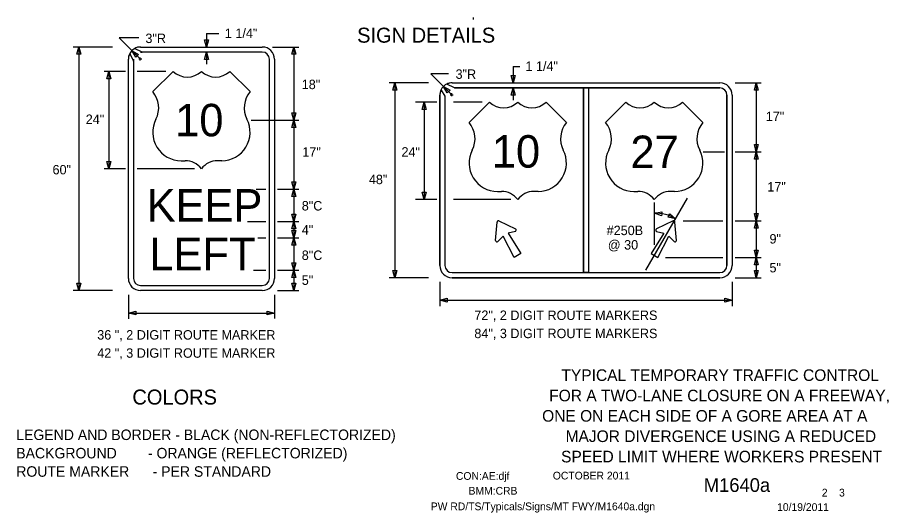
# Model space of a CAD drawing. Extents: x 16512 to 19504, y 5761 to 6984.
# Drawn here: x 17768 to 18466, y 5932 to 6328 of the extents above; entities that cross this region are included whole.
import ezdxf

# ---------------------------------------------------------------- set-up
doc = ezdxf.new("R2010")
doc.units = 0
for name, color, linetype in [('ALI_LEGAL_EX', 7, 'Continuous'), ('BORDER', 7, 'Continuous'), ('BORDER_SIGNAL_WO', 7, 'Continuous'), ('TRAFFIC_SIGNS_PR', 7, 'Continuous'), ('TYPICAL_EX', 7, 'Continuous'), ('TYPICAL_TEXT_DIMEN_PR', 7, 'Continuous')]:
    doc.layers.add(name, color=color, linetype=linetype)

msp = doc.modelspace()

# ---------------------------------------------------------------- linework, layer by layer
at = {"layer": 'ALI_LEGAL_EX'}
msp.add_lwpolyline([(18133.42, 6328.26), (18133.42, 6326.51)], dxfattribs=at)
at = {"layer": 'TRAFFIC_SIGNS_PR'}
for p, q in [((17859.5, 6300.96), (17858.5, 6299.45)), ((17868.29, 6300.52), (17862.19, 6303.27)), ((17867.09, 6304.58), (17964.59, 6304.58)), ((17857.34, 6119.33), (17857.34, 6294.83)), ((17858.53, 6299.39), (17861.4, 6293.35)), ((17861.4, 6294.83), (17861.4, 6119.33)), ((17964.59, 6300.52), (17867.09, 6300.52)), ((17970.27, 6119.33), (17970.27, 6294.83)), ((17974.34, 6294.83), (17974.34, 6119.33)), ((18118.56, 6271.83), (18112.33, 6274.85)), ((18116.61, 6275.88), (18331.11, 6275.88)), ((18116.61, 6275.88), (18331.11, 6275.88)), ((18106.86, 6266.13), (18106.86, 6129.63)), ((18106.86, 6129.63), (18106.86, 6266.13)), ((18107.78, 6270.14), (18110.91, 6265.1)), ((18118.55, 6271.82), (18221.83, 6271.82)), ((18331.11, 6271.82), (18118.55, 6271.82)), ((18221.83, 6271.82), (18221.83, 6123.95)), ((18225.89, 6271.82), (18225.89, 6123.95)), ((18225.89, 6271.82), (18331.11, 6271.82)), ((18336.8, 6266.13), (18336.8, 6220.38)), ((18336.8, 6129.63), (18336.8, 6266.13)), ((18340.86, 6266.13), (18340.86, 6129.63)), ((18340.86, 6266.13), (18340.86, 6129.63)), ((18110.92, 6265.08), (18110.92, 6129.63)), ((18110.92, 6265.08), (18110.92, 6129.63)), ((18336.8, 6220.38), (18336.8, 6129.63)), ((18151.46, 6149.74), (18152.61, 6164.46)), ((18154.12, 6165.33), (18167.44, 6158.97)), ((18293.59, 6165.33), (18280.28, 6158.97)), ((18296.26, 6149.74), (18295.1, 6164.46)), ((18116.61, 6123.95), (18331.11, 6123.95)), ((18116.61, 6119.88), (18331.11, 6119.88)), ((18331.11, 6119.88), (18116.61, 6119.88)), ((17867.09, 6113.64), (17964.59, 6113.64)), ((17964.59, 6109.58), (17867.09, 6109.58))]:
    msp.add_line(p, q, dxfattribs=at)
for points in [[(18118.55, 6271.82), (18118.53, 6271.83)], [(18110.91, 6265.1), (18110.92, 6265.08)], [(18167.28, 6157), (18161.55, 6155.42), (18171.77, 6139.25), (18166.37, 6136.13), (18157.48, 6153.07), (18153.25, 6148.9)], [(18280.44, 6157), (18286.16, 6155.42), (18275.95, 6139.25), (18281.34, 6136.13), (18290.24, 6153.07), (18294.46, 6148.9)]]:
    msp.add_lwpolyline(points, dxfattribs=at)
msp.add_lwpolyline([(18221.83, 6271.82), (18225.89, 6271.82), (18225.89, 6123.95), (18221.83, 6123.95)], close=True, dxfattribs=at)
for centre, radius, start, end in [((17867.09, 6294.83), 9.75, 90, 180), ((17866.5, 6297.01), 7.6, 85.58319, 124.53531), ((17964.59, 6294.83), 9.75, 0, 90), ((17864.37, 6295.43), 7.06, 145.86811, 184.82317), ((17855.94, 6294.09), 5.51, 352.24294, 7.75653), ((17867.69, 6304.95), 4.47, 262.2432, 277.7568), ((17964.59, 6294.83), 5.69, 0, 90), ((18116.61, 6266.13), 9.75, 90, 180), ((18116.61, 6266.13), 9.75, 90, 180), ((18115.93, 6269.32), 6.6, 84.11162, 123.06374), ((18331.11, 6266.13), 9.75, 0, 90), ((18331.11, 6266.13), 9.75, 0, 90), ((18112.99, 6266.84), 6.17, 147.60925, 186.56283), ((18117.55, 6279), 7.24, 277.81035, 278.05403), ((18331.11, 6266.13), 5.69, 0, 89.99421), ((18331.11, 6266.13), 5.69, 0, 90), ((18153.67, 6164.37), 1.06, 64.48226, 175.51774), ((18294.05, 6164.37), 1.06, 4.48226, 115.51774), ((18166.98, 6158.02), 1.06, 285.9885, 64.48226), ((18280.73, 6158.02), 1.06, 115.51774, 254.0115), ((18152.52, 6149.66), 1.06, 175.51775, 314.01151), ((18295.2, 6149.66), 1.06, 225.98849, 4.48225), ((18116.61, 6129.63), 9.75, 180, 270), ((18116.61, 6129.63), 9.75, 180, 270), ((18116.61, 6129.63), 5.69, 180, 270), ((18116.61, 6129.63), 5.69, 180, 270), ((18331.11, 6129.63), 9.75, 270, 0), ((18331.11, 6129.63), 5.69, 270, 0), ((18331.11, 6129.63), 9.75, 270, 0), ((18331.11, 6129.63), 5.69, 270, 0), ((17867.09, 6119.33), 9.75, 180, 270), ((17867.09, 6119.33), 5.69, 180, 270), ((17964.59, 6119.33), 5.69, 270, 0), ((17964.59, 6119.33), 9.75, 270, 0)]:
    msp.add_arc(centre, radius, start, end, dxfattribs=at)
at = {"layer": 'TYPICAL_EX'}
for p, q in [((17876.84, 6268.84), (17893.09, 6285.09)), ((17954.84, 6268.84), (17938.59, 6285.09)), ((18130.22, 6244.22), (18146.47, 6260.47)), ((18208.22, 6244.22), (18191.97, 6260.47)), ((18239.5, 6244.22), (18255.75, 6260.47)), ((18317.5, 6244.22), (18301.25, 6260.47)), ((17899.56, 6213.54), (17902.81, 6213.54)), ((17932.11, 6213.54), (17928.86, 6213.54)), ((18152.95, 6188.93), (18156.2, 6188.93)), ((18185.49, 6188.93), (18182.24, 6188.93)), ((18262.22, 6188.93), (18265.47, 6188.93)), ((18294.77, 6188.93), (18291.52, 6188.93))]:
    msp.add_line(p, q, dxfattribs=at)
for centre, radius, start, end in [((17904.46, 6296.92), 16.42, 226.14041, 313.85958), ((17927.21, 6296.92), 16.42, 226.14042, 313.85959), ((17861.44, 6255.82), 20.16, 333.09768, 40.19361), ((17970.24, 6255.82), 20.16, 139.80639, 206.90233), ((18157.85, 6272.31), 16.42, 226.14041, 313.85958), ((18180.59, 6272.31), 16.42, 226.14042, 313.85959), ((18267.12, 6272.31), 16.42, 226.14041, 313.85958), ((18289.87, 6272.31), 16.42, 226.14042, 313.85959), ((17899.6, 6236.27), 22.73, 152.6698, 269.90132), ((17932.07, 6236.27), 22.73, 270.09868, 27.3302), ((18114.82, 6231.21), 20.16, 333.09768, 40.19361), ((18223.62, 6231.21), 20.16, 139.80639, 206.90233), ((18224.1, 6231.21), 20.16, 333.09768, 40.19361), ((18332.9, 6231.21), 20.16, 139.80639, 206.90233), ((18152.99, 6211.66), 22.73, 152.6698, 269.90132), ((18185.45, 6211.66), 22.73, 270.09868, 27.3302), ((18262.27, 6211.66), 22.73, 152.6698, 269.90132), ((18294.73, 6211.66), 22.73, 270.09868, 27.3302), ((17902.85, 6197.26), 16.28, 37.1038, 90.13853), ((17928.82, 6197.26), 16.28, 89.86147, 142.8962), ((18156.24, 6172.65), 16.28, 37.1038, 90.13853), ((18182.2, 6172.65), 16.28, 89.86147, 142.8962), ((18265.52, 6172.65), 16.28, 37.1038, 90.13853), ((18291.48, 6172.65), 16.28, 89.86147, 142.8962)]:
    msp.add_arc(centre, radius, start, end, dxfattribs=at)
at = {"layer": 'TYPICAL_TEXT_DIMEN_PR'}
for p, q in [((17919.81, 6315.34), (17919.81, 6304.58)), ((17919.81, 6315.34), (17929.91, 6315.34)), ((17865.71, 6311.86), (17850.05, 6311.86)), ((17850.05, 6311.86), (17860.29, 6301.63)), ((17919.81, 6304.58), (17918.24, 6310.44)), ((17918.24, 6310.44), (17919.81, 6310.44)), ((17919.81, 6310.44), (17921.38, 6310.44)), ((17921.38, 6310.44), (17919.81, 6304.58)), ((17844.51, 6304.58), (17813.21, 6304.58)), ((17815.98, 6298.72), (17817.55, 6304.58)), ((17817.55, 6304.58), (17817.55, 6109.58)), ((17817.55, 6304.58), (17819.12, 6298.72)), ((17860.29, 6301.63), (17866.85, 6295.07)), ((17863.32, 6296.37), (17860.29, 6301.63)), ((17860.29, 6301.63), (17865.54, 6298.6)), ((17972.88, 6304.58), (17993.84, 6304.58)), ((17988.37, 6298.72), (17989.94, 6304.58)), ((17989.94, 6304.58), (17989.94, 6246.08)), ((17989.94, 6304.58), (17991.51, 6298.72)), ((17817.55, 6298.72), (17815.98, 6298.72)), ((17819.12, 6298.72), (17817.55, 6298.72)), ((17864.43, 6297.49), (17863.32, 6296.37)), ((17865.54, 6298.6), (17864.43, 6297.49)), ((17865.64, 6295.07), (17868.05, 6295.07)), ((17866.85, 6293.86), (17866.85, 6296.28)), ((17918.28, 6294.66), (17919.86, 6300.52)), ((17919.86, 6294.66), (17918.28, 6294.66)), ((17919.86, 6300.52), (17919.86, 6290.77)), ((17919.86, 6300.52), (17921.43, 6294.66)), ((17921.43, 6294.66), (17919.86, 6294.66)), ((17989.94, 6298.72), (17988.37, 6298.72)), ((17991.51, 6298.72), (17989.94, 6298.72)), ((18165.47, 6289.03), (18165.47, 6275.88)), ((18165.47, 6289.03), (18170.99, 6289.03)), ((17854.96, 6285.08), (17837.84, 6285.08)), ((17840.16, 6279.22), (17841.73, 6285.08)), ((17841.73, 6285.08), (17841.73, 6207.08)), ((17841.73, 6285.08), (17843.3, 6279.22)), ((17887.2, 6285.08), (17864.33, 6285.08)), ((18113.75, 6283.17), (18099.57, 6283.17)), ((18099.57, 6283.17), (18109.72, 6273.02)), ((18165.47, 6275.88), (18163.89, 6281.74)), ((18163.89, 6281.74), (18165.47, 6281.74)), ((18165.47, 6281.74), (18167.04, 6281.74)), ((18167.04, 6281.74), (18165.47, 6275.88)), ((17841.73, 6279.22), (17840.16, 6279.22)), ((17843.3, 6279.22), (17841.73, 6279.22)), ((18097.62, 6275.88), (18066.33, 6275.88)), ((18069.1, 6270.02), (18070.67, 6275.88)), ((18070.67, 6275.88), (18070.67, 6119.88)), ((18070.67, 6275.88), (18072.24, 6270.02)), ((18109.72, 6273.02), (18116.37, 6266.37)), ((18112.76, 6267.76), (18109.72, 6273.02)), ((18109.72, 6273.02), (18114.98, 6269.99)), ((18343.23, 6275.88), (18364.19, 6275.88)), ((18358.72, 6270.02), (18360.29, 6275.88)), ((18360.29, 6275.88), (18360.29, 6220.63)), ((18360.29, 6275.88), (18361.86, 6270.02)), ((18070.67, 6270.02), (18069.1, 6270.02)), ((18072.24, 6270.02), (18070.67, 6270.02)), ((18113.87, 6268.88), (18112.76, 6267.76)), ((18114.98, 6269.99), (18113.87, 6268.88)), ((18115.16, 6266.37), (18117.58, 6266.37)), ((18116.37, 6265.16), (18116.37, 6267.58)), ((18163.94, 6265.96), (18165.51, 6271.82)), ((18163.94, 6265.96), (18165.51, 6271.82)), ((18165.51, 6271.82), (18165.51, 6262.07)), ((18165.51, 6271.82), (18167.08, 6265.96)), ((18165.51, 6271.82), (18167.08, 6265.96)), ((18360.29, 6270.02), (18358.72, 6270.02)), ((18361.86, 6270.02), (18360.29, 6270.02)), ((18104.49, 6260.47), (18087.36, 6260.47)), ((18092.65, 6254.61), (18094.23, 6260.47)), ((18094.23, 6260.47), (18094.23, 6182.47)), ((18094.23, 6260.47), (18095.8, 6254.61)), ((18140.59, 6260.47), (18117.71, 6260.47)), ((18165.51, 6265.96), (18163.94, 6265.96)), ((18165.51, 6265.96), (18163.94, 6265.96)), ((18167.08, 6265.96), (18165.51, 6265.96)), ((18167.08, 6265.96), (18165.51, 6265.96)), ((18094.23, 6254.61), (18092.65, 6254.61)), ((18095.8, 6254.61), (18094.23, 6254.61)), ((17955.73, 6246.08), (17993.84, 6246.08)), ((17989.94, 6246.08), (17988.37, 6251.94)), ((17988.37, 6251.94), (17989.94, 6251.94)), ((17988.37, 6240.22), (17989.94, 6246.08)), ((17989.94, 6251.94), (17991.51, 6251.94)), ((17991.51, 6251.94), (17989.94, 6246.08)), ((17989.94, 6246.08), (17989.94, 6190.83)), ((17989.94, 6246.08), (17991.51, 6240.22)), ((17989.94, 6240.22), (17988.37, 6240.22)), ((17991.51, 6240.22), (17989.94, 6240.22)), ((18360.29, 6220.63), (18358.72, 6226.49)), ((18358.72, 6226.49), (18360.29, 6226.49)), ((18360.29, 6226.49), (18361.86, 6226.49)), ((18361.86, 6226.49), (18360.29, 6220.63)), ((18317.67, 6220.63), (18334.82, 6220.63)), ((18343.23, 6220.63), (18364.19, 6220.63)), ((18358.72, 6214.77), (18360.29, 6220.63)), ((18360.29, 6220.63), (18360.29, 6165.38)), ((18360.29, 6220.63), (18361.86, 6214.77)), ((17841.73, 6207.08), (17840.16, 6212.94)), ((17840.16, 6212.94), (17841.73, 6212.94)), ((17841.73, 6212.94), (17843.3, 6212.94)), ((17843.3, 6212.94), (17841.73, 6207.08)), ((18360.29, 6214.77), (18358.72, 6214.77)), ((18361.86, 6214.77), (18360.29, 6214.77)), ((17854.96, 6207.08), (17837.84, 6207.08)), ((17910.33, 6207.08), (17864.33, 6207.08)), ((17989.94, 6190.83), (17988.37, 6196.69)), ((17988.37, 6196.69), (17989.94, 6196.69)), ((17989.94, 6196.69), (17991.51, 6196.69)), ((17991.51, 6196.69), (17989.94, 6190.83)), ((17959.66, 6190.83), (17967.35, 6190.83)), ((17976.71, 6190.83), (17993.84, 6190.83)), ((17988.37, 6184.97), (17989.94, 6190.83)), ((17989.94, 6190.83), (17989.94, 6164.83)), ((17989.94, 6190.83), (17991.51, 6184.97)), ((17989.94, 6184.97), (17988.37, 6184.97)), ((17991.51, 6184.97), (17989.94, 6184.97)), ((18104.49, 6182.47), (18087.36, 6182.47)), ((18094.23, 6182.47), (18092.65, 6188.33)), ((18092.65, 6188.33), (18094.23, 6188.33)), ((18094.23, 6188.33), (18095.8, 6188.33)), ((18095.8, 6188.33), (18094.23, 6182.47)), ((18163.71, 6182.47), (18117.71, 6182.47)), ((18271.89, 6125.98), (18305.13, 6183.57)), ((18278.65, 6146.14), (18278.65, 6180.13)), ((17989.94, 6164.83), (17988.37, 6170.69)), ((17988.37, 6170.69), (17989.94, 6170.69)), ((17989.94, 6170.69), (17991.51, 6170.69)), ((17991.51, 6170.69), (17989.94, 6164.83)), ((18278.67, 6171.58), (18284.67, 6172.54)), ((18284.35, 6169.41), (18278.67, 6171.58)), ((18284.51, 6170.97), (18284.35, 6169.41)), ((18284.67, 6172.54), (18284.51, 6170.97)), ((18289.66, 6168.25), (18290.34, 6169.67)), ((18290.34, 6169.67), (18291.03, 6171.08)), ((18291.03, 6171.08), (18295.62, 6167.12)), ((18360.29, 6165.38), (18358.72, 6171.24)), ((18358.72, 6171.24), (18360.29, 6171.24)), ((18360.29, 6171.24), (18361.86, 6171.24)), ((18361.86, 6171.24), (18360.29, 6165.38)), ((17952.65, 6164.83), (17967.35, 6164.83)), ((17976.71, 6164.83), (17993.84, 6164.83)), ((17988.37, 6158.97), (17989.94, 6164.83)), ((17989.94, 6164.83), (17989.94, 6151.83)), ((17989.94, 6164.83), (17991.51, 6158.97)), ((18295.62, 6167.12), (18289.66, 6168.25)), ((18301.6, 6165.38), (18333.47, 6165.38)), ((18343.23, 6165.38), (18364.19, 6165.38)), ((18358.72, 6159.52), (18360.29, 6165.38)), ((18360.29, 6165.38), (18360.29, 6136.13)), ((18360.29, 6165.38), (18361.86, 6159.52)), ((17989.94, 6158.97), (17988.37, 6158.97)), ((17989.94, 6151.83), (17988.37, 6157.69)), ((17988.37, 6157.69), (17989.94, 6157.69)), ((17991.51, 6158.97), (17989.94, 6158.97)), ((17989.94, 6157.69), (17991.51, 6157.69)), ((17991.51, 6157.69), (17989.94, 6151.83)), ((18360.29, 6159.52), (18358.72, 6159.52)), ((18361.86, 6159.52), (18360.29, 6159.52)), ((17961, 6151.83), (17967.35, 6151.83)), ((17976.71, 6151.83), (17993.84, 6151.83)), ((17988.37, 6145.97), (17989.94, 6151.83)), ((17989.94, 6151.83), (17989.94, 6125.83)), ((17989.94, 6151.83), (17991.51, 6145.97)), ((17989.94, 6145.97), (17988.37, 6145.97)), ((17991.51, 6145.97), (17989.94, 6145.97)), ((18360.29, 6136.13), (18358.72, 6141.99)), ((18358.72, 6141.99), (18360.29, 6141.99)), ((18360.29, 6141.99), (18361.86, 6141.99)), ((18361.86, 6141.99), (18360.29, 6136.13)), ((18287.46, 6136.13), (18333.47, 6136.13)), ((18343.23, 6136.13), (18364.19, 6136.13)), ((18358.72, 6130.27), (18360.29, 6136.13)), ((18360.29, 6136.13), (18360.29, 6119.88)), ((18360.29, 6136.13), (18361.86, 6130.27)), ((17989.94, 6125.83), (17988.37, 6131.69)), ((17988.37, 6131.69), (17989.94, 6131.69)), ((17989.94, 6131.69), (17991.51, 6131.69)), ((17991.51, 6131.69), (17989.94, 6125.83)), ((18360.29, 6130.27), (18358.72, 6130.27)), ((18361.86, 6130.27), (18360.29, 6130.27)), ((17957.5, 6125.83), (17967.35, 6125.83)), ((17976.71, 6125.83), (17993.84, 6125.83)), ((17988.37, 6119.97), (17989.94, 6125.83)), ((17989.94, 6119.97), (17988.37, 6119.97)), ((17989.94, 6125.83), (17989.94, 6109.58)), ((17989.94, 6125.83), (17991.51, 6119.97)), ((17991.51, 6119.97), (17989.94, 6119.97)), ((18097.62, 6119.88), (18066.33, 6119.88)), ((18070.67, 6119.88), (18069.1, 6125.74)), ((18069.1, 6125.74), (18070.67, 6125.74)), ((18070.67, 6125.74), (18072.24, 6125.74)), ((18072.24, 6125.74), (18070.67, 6119.88)), ((18343.23, 6119.88), (18360.36, 6119.88)), ((18343.23, 6119.88), (18364.19, 6119.88)), ((18343.23, 6119.88), (18360.36, 6119.88)), ((18360.29, 6119.88), (18358.72, 6125.74)), ((18358.72, 6125.74), (18360.29, 6125.74)), ((18360.29, 6125.74), (18361.86, 6125.74)), ((18361.86, 6125.74), (18360.29, 6119.88)), ((17817.55, 6109.58), (17815.98, 6115.44)), ((17815.98, 6115.44), (17817.55, 6115.44)), ((17817.55, 6115.44), (17819.12, 6115.44)), ((17819.12, 6115.44), (17817.55, 6109.58)), ((17989.94, 6109.58), (17988.37, 6115.44)), ((17988.37, 6115.44), (17989.94, 6115.44)), ((17989.94, 6115.44), (17991.51, 6115.44)), ((17991.51, 6115.44), (17989.94, 6109.58)), ((18106.86, 6116.54), (18106.86, 6096.98)), ((18340.86, 6116.54), (18340.86, 6096.98)), ((17844.51, 6109.58), (17813.21, 6109.58)), ((17857.34, 6106.24), (17857.34, 6086.89)), ((17974.34, 6106.24), (17974.34, 6087.34)), ((17976.71, 6109.58), (17993.84, 6109.58)), ((18106.86, 6101.91), (18112.72, 6103.48)), ((18106.86, 6101.91), (18340.86, 6101.91)), ((18112.72, 6100.34), (18106.86, 6101.91)), ((18112.72, 6103.48), (18112.72, 6101.91)), ((18112.72, 6101.91), (18112.72, 6100.34)), ((18335, 6101.91), (18335, 6103.48)), ((18335, 6103.48), (18340.86, 6101.91)), ((18340.86, 6101.91), (18335, 6100.34)), ((18335, 6100.34), (18335, 6101.91)), ((17857.34, 6091.61), (17863.2, 6093.18)), ((17857.34, 6091.61), (17974.34, 6091.61)), ((17863.2, 6090.04), (17857.34, 6091.61)), ((17863.2, 6093.18), (17863.2, 6091.61)), ((17863.2, 6091.61), (17863.2, 6090.04)), ((17968.47, 6091.61), (17968.47, 6093.18)), ((17968.47, 6093.18), (17974.34, 6091.61)), ((17974.34, 6091.61), (17968.47, 6090.04)), ((17968.47, 6090.04), (17968.47, 6091.61))]:
    msp.add_line(p, q, dxfattribs=at)
msp.add_arc((18278.84, 6137.14), 34.39, 60.74521, 90.32117, dxfattribs=at)

# ---------------------------------------------------------------- texts
at = {"layer": 'BORDER'}
for s, p in [('TYPICAL TEMPORARY TRAFFIC CONTROL', (18204.21, 6037.21)), ('FOR A TWO-LANE CLOSURE ON A FREEWAY,', (18194.41, 6020.91)), ('ONE ON EACH SIDE OF A GORE AREA AT A ', (18188.75, 6004.62)), ('MAJOR DIVERGENCE USING A REDUCED', (18207.52, 5988.32)), ('SPEED LIMIT WHERE WORKERS PRESENT', (18203.92, 5972.02))]:
    msp.add_text(s, height=9.3, dxfattribs=at).set_placement(p)
at = {"layer": 'BORDER_SIGNAL_WO'}
for s, height, p in [('CON:AE:djf  ', 6.2, (18119.69, 5958.06)), ('    OCTOBER 2011    ', 6.2, (18188.08, 5958.34)), ('    M1640a   ', 11, (18301.86, 5948.38)), ('BMM:CRB   ', 6.2, (18129.81, 5946.17)), (' 2    3 ', 6.2, (18410.45, 5944.7)), ('PW RD/TS/Typicals/Signs/MT FWY/M1640a.dgn      ', 6.2, (18099.55, 5933.71)), ('10/19/2011', 6.2, (18376.93, 5933.13))]:
    msp.add_text(s, height=height, dxfattribs=at).set_placement(p)
at = {"layer": 'TRAFFIC_SIGNS_PR'}
for s, p in [('10', (17894.81, 6233.08)), ('10', (18148.46, 6208.01)), ('27', (18259.47, 6207.65)), ('KEEP', (17871.94, 6164.83)), ('LEFT', (17874.17, 6125.83))]:
    msp.add_text(s, height=26, dxfattribs=at).set_placement(p)
at = {"layer": 'TYPICAL_TEXT_DIMEN_PR'}
for s, height, p in [('3"R', 7.55, (17870.98, 6307.74)), ('1 1/4"', 7.55, (17934.61, 6311.84)), ('SIGN DETAILS', 12, (18040.56, 6308.05)), ('1 1/4"', 7.55, (18175.39, 6285.46)), ('3"R', 7.55, (18119.39, 6279.09)), ('18"', 7.55, (17996.18, 6270.85)), ('17"', 7.55, (18367.87, 6245.24)), ('24"', 7.55, (17823.18, 6242.97)), ('17"', 7.55, (17996.64, 6216.81)), ('24"', 7.55, (18076.08, 6216.8)), ('60"', 7.55, (17796.58, 6202.6)), ('48"', 7.55, (18049.97, 6194.78)), ('17"', 7.55, (18369.07, 6188.89)), ('8"C', 7.55, (17996.21, 6173.69)), ('4" ', 7.55, (17996.21, 6154.43)), ('#250B', 7.55, (18240.42, 6153.98)), ('9"', 7.55, (18370.85, 6147.23)), ('@ 30', 7.55, (18241.36, 6142.43)), ('8"C', 7.55, (17996.21, 6134.1)), ('5"', 7.55, (18370.85, 6124.13)), ('5" ', 7.55, (17996.21, 6114.13)), ('72", 2 DIGIT ROUTE MARKERS', 7.55, (18134.44, 6086.05)), ('36 ", 2 DIGIT ROUTE MARKER', 7.55, (17832.38, 6070.35)), ('84", 3 DIGIT ROUTE MARKERS', 7.55, (18134.44, 6071.5)), ('42 ", 3 DIGIT ROUTE MARKER', 7.55, (17832.38, 6055.8)), ('COLORS', 12, (17860.53, 6018.33)), ('LEGEND AND BORDER - BLACK (NON-REFLECTORIZED)', 8.4, (17767.53, 5989.92)), ('BACKGROUND        - ORANGE (REFLECTORIZED)', 8.4, (17767.53, 5975.22)), ('ROUTE MARKER      - PER STANDARD', 8.4, (17767.53, 5960.52))]:
    msp.add_text(s, height=height, dxfattribs=at).set_placement(p)

doc.saveas('drawing.dxf')
